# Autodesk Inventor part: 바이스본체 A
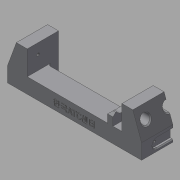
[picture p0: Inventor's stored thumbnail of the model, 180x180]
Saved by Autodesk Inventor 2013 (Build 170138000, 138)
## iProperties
Created: 2017-04
Part Number: 바이스본체 A
Material: 일반
Document SubType Name: Modeling
Designer: mduedu
Density: 1 g/cm^3
Author: mduedu
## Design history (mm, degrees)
sketch "스케치1"
  geometry: L1 (-75, 0)-(75, 0); L2 (-75, 0)-(-75, 17); L3 (-53, 17)-(53, 17); L4 (75, 17)-(75, 0); L5 (-75, 17)-(-65.173, 44); L6 (-65.173, 44)-(-53, 44); L7 (-53, 44)-(-53, 17); L8 (0, 0)-(0, 17); L9 (75, 17)-(65.173, 44); L10 (65.173, 44)-(53, 44); L11 (53, 44)-(53, 17); 1 further point
  constraints: 22 end point, 4 perpendicular, 2 horizontal alignment, 2 midpoint, 2 symmetric about line, 1 coincident, 1 collinear, 1 horizontal, 1 vertical
  dimensions: "d0" = 150 distance of L1.start L1.end; "d1" = 17 distance of L1.start L2.end; "d2" = 27 distance of L3.start L6.end; "d3" = 22 distance of L3.start L2.end; "d4" = 70 deg angle of L3 L5; "d54" = 20 deg angle of L9 L4
extrude "돌출1" new body sketch "스케치1" stored distance "d5" = 70; taper "d6" = 0 deg
sketch "스케치2"
  geometry: L1 (0, 70)-(106, 70) reference; L2 (106, 70)-(106, 0) reference; L3 (106, 0)-(0, 0) reference; L4 (0, 47)-(106, 47); L5 (106, 47)-(106, 23); L6 (106, 23)-(0, 23); L7 (0, 23)-(0, 47); L8 (0, 70)-(0, 0) reference; 2 further points
  constraints: 8 end point, 2 parallel, 2 point on line, 1 horizontal, 1 horizontal alignment, 1 midpoint, 1 perpendicular
  dimensions: "d7" = 24 distance between parallel lines of L6 L4
extrude "돌출2" cut sketch "스케치2" stored distance "d9" = 70; taper "d10" = 0 deg
sketch "스케치3"
  geometry: L1 (22, -23)-(128, -23) reference; L2 (128, -47)-(22, -47) reference; L3 (22, -18)-(128, -18); L4 (128, -52)-(22, -52); L5 (22, -18)-(22, -52); L6 (128, -18)-(128, -52); 1 further point
  constraints: 8 end point, 3 parallel, 2 point on line, 1 perpendicular
  dimensions: "d11" = 5 distance between parallel lines of L3 L1; "d12" = 5 distance between parallel lines of L4 L2
extrude "돌출3" cut sketch "스케치3" distance "d13" = 12; taper "d14" = 0 deg
fillet "모깎기1" dims "d15" = 3, "d16" = 3
sketch "스케치4"
  geometry: L1 (103, 23)-(3, 23) reference; L2 (0, 26)-(0, 0) reference; L3 (106, 0)-(0, 0) reference; L4 (106, 26)-(106, 0) reference; L5 (96, 0)-(90, 0); L6 (90, 0)-(90, 19.5); L7 (96, 19.5)-(96, 0); L8 (90, 19.5)-(96, 19.5); A1 r 3 centre (3, 26) between (0, 26) and (3, 23) reference; A2 r 3 centre (103, 26) between (103, 23) and (106, 26) reference; 1 further point
  constraints: 8 end point, 2 perpendicular, 1 horizontal, 1 parallel, 1 point on line
  dimensions: "d17" = 10 distance between parallel lines of L7 L4; "d18" = 6 distance between parallel lines of L7 L6; "d27" = 3.5 distance between parallel lines of L8 L1
extrude "돌출4" join sketch "스케치4" distance "d19" = 12; taper "d20" = 0 deg
chamfer "모따기1" distance "d21" = 3; stored, may be unused: second distance "d22" = 2, angle "d23" = 45 deg
chamfer "모따기2" distance "d24" = 3; stored, may be unused: second distance "d25" = 2, angle "d26" = 45 deg
sketch "스케치5"
  geometry: L1 (-15.5, 35.8)-(-15.5, -25.8) reference; L2 (19.5, 0)-(0, 0) reference; C1 r 6.5 at (9.5, 15); 1 further point
  constraints: 1 centre point
  dimensions: "d28" = 13 diameter of C1; "d30" = 15 distance from line of C1.centre L2; "d31" = 25 distance from line of C1.centre L1
extrude "돌출5" cut sketch "스케치5" stored distance "d32" = 12; taper "d33" = 0 deg
sketch "스케치6"
  geometry: C1 r 5 at (-10, 15); C2 r 5 at (-60, 15); A1 r 6.5 centre (-10, 15) between (-15.766, 12) and (-4.234, 12) reference; A2 r 6.5 centre (-60, 15) between (-65.766, 12) and (-54.234, 12) reference; 1 further point
  constraints: 2 centre point, 2 coincident
  dimensions: "d34" = 10 diameter of C1; "d35" = 10 diameter of C2 (= d34)
extrude "돌출6" cut sketch "스케치6" stored distance "d36" = 12; taper "d37" = 0 deg
chamfer "모따기3" distance "d38" = 1; stored, may be unused: second distance "d39" = 2, angle "d40" = 45 deg
chamfer "모따기4" distance "d41" = 1; stored, may be unused: second distance "d42" = 2, angle "d43" = 45 deg
sketch "스케치7"
  geometry: L1 (-35, 35.8)-(-35, -25.8) reference; L2 (-70, 0)-(0, 0) reference; C1 r 5 at (-35, 15); 1 further point
  constraints: 1 centre point, 1 point on line
  dimensions: "d44" = 10 diameter of C1; "d45" = 15 distance from line of C1.centre L2
extrude "돌출7" cut sketch "스케치7" stored distance "d46" = 12; taper "d47" = 0 deg
chamfer "모따기5" distance "d48" = 1; stored, may be unused: second distance "d49" = 2, angle "d50" = 45 deg
node "작업축1"
sketch "스케치8"
  geometry: L1 (-105, 32)-(105, 32) reference; L2 (58, 32)-(64, 32); L3 (64, 32)-(64, 40); L4 (64, 40)-(58, 40); L5 (58, 40)-(58, 32); L6 (53, 38)-(53, 26) reference; 1 further point
  constraints: 8 end point, 2 parallel, 1 horizontal, 1 perpendicular, 1 point on line
  dimensions: "d51" = 5 distance from line of L6 L2.start; "d52" = 6 distance of L3.end L4.end; "d53" = 16 diameter of L4 L1
revolve "회전1" sketch "스케치8" stored, may be unused: angle "d55" = 90 deg
fillet "모깎기2"
chamfer "모따기6" distance "d56" = 1; stored, may be unused: second distance "d57" = 2, angle "d58" = 45 deg
sketch "스케치9"
  geometry: L1 (17.5, 3)-(52.5, 3); L2 (52.5, 13)-(17.5, 13); L3 (70, 0)-(0, 0) reference; L4 (17.5, 8)-(52.5, 8); A1 r 5 centre (17.5, 8) between (17.5, 13) and (17.5, 3); A2 r 5 centre (52.5, 8) between (52.5, 3) and (52.5, 13); 3 further points
  constraints: 6 end point, 4 point on circle, 3 tangent, 2 centre point, 2 midpoint, 2 parallel, 1 horizontal, 1 vertical alignment
  dimensions: "d59" = 35 distance of L4.start L4.end; "d61" = 5 radius of A2; "d62" = 8 distance between parallel lines of L3 L4
extrude "돌출8" cut sketch "스케치9" distance "d63" = 3; taper "d64" = 0 deg
chamfer "모따기7" distance "d65" = 1; stored, may be unused: second distance "d66" = 2, angle "d67" = 45 deg
chamfer "모따기8" distance "d68" = 1; stored, may be unused: second distance "d69" = 2, angle "d70" = 45 deg
feature "분할1"
sketch "스케치10"
  geometry: L1 (35, 27)-(0, 27) reference; L2 (0, 0)-(0, 27) reference; 1 further point
  dimensions: "d85" = 11.5 distance from line of point (12, 15.5) L1; "d86" = 12 distance from line of point (12, 15.5) L2
hole "구멍1" sketch "스케치10" at (12, 15.5) diameter "d71" = 3.242; stored, may be unused: countersink angle "d75" = 90 deg, drill point angle "d77" = 120 deg; dims "d72" = 6, "d73" = 4, "d74" = 2, "d76" = 8
sketch "스케치11"
  geometry: A1 r 5 centre (17.5, 8) between (17.5, 13) and (17.5, 3) reference; 1 further point
  constraints: 1 coincident
hole "구멍3" sketch "스케치11" at (17.5, 8) diameter "d78" = 2.459; stored, may be unused: countersink angle "d82" = 90 deg, drill point angle "d84" = 120 deg; dims "d79" = 4.5, "d80" = 4, "d81" = 2, "d83" = 6
sketch "스케치12"
  geometry: L1 (-75, 0)-(75, 0) reference; 3 further points
  constraints: 1 midpoint, 1 vertical alignment, 1 other
  dimensions: "d87" = 8 distance of point (0, 8) point (0, 0)
feature "엠보싱1" sketch "스케치12" dims "d7" = 24, "d88" = 0.5, "d89" = 0
node "솔리드1"
mirror "대칭1"
mirror "대칭2"
mirror "대칭3"
mirror "대칭4"
node "투영된 루프1"
